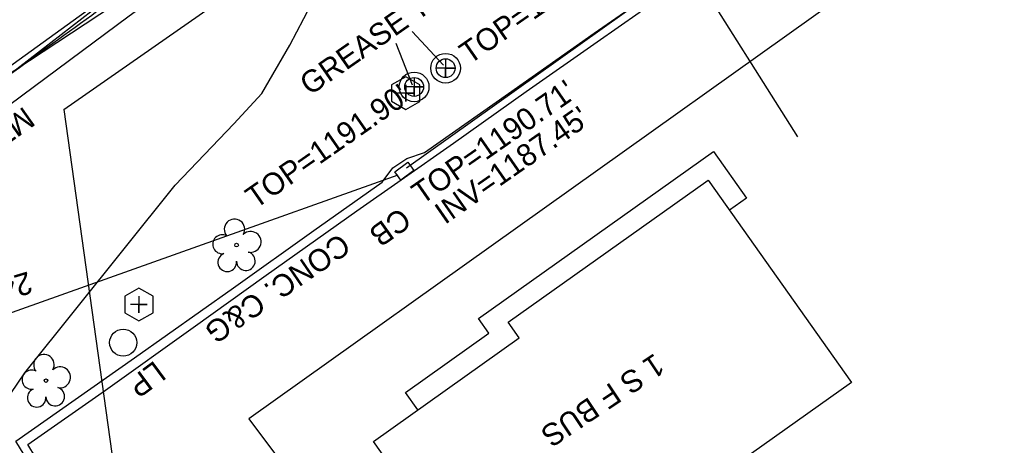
# Model space of a CAD drawing. Extents: x 1262092 to 1264624, y 774970 to 778314.
# Drawn here: x 1263560.4 to 1263737.4, y 776596.1 to 776673.4 of the extents above; entities that cross this region are included whole.
import ezdxf

# ---------------------------------------------------------------- set-up
doc = ezdxf.new("R2010")
doc.units = 0
for name, color, linetype in [('COGO Default Parcel', 7, 'Continuous'), ('Exist Horizontal Alignment Tick Small', 7, 'Continuous'), ('Exist Right of Way Line', 7, 'Continuous'), ('Exist Roads Curbs', 7, 'Continuous'), ('Exist Roads EOP', 7, 'Continuous'), ('Exist Roads EOP Other', 7, 'Continuous'), ('Exist Roads EOT', 7, 'Continuous'), ('Exist Structure Minor Catch Basin', 7, 'Continuous'), ('Exist Structure Minor Catch Basin Text', 7, 'Continuous'), ('Exist Structure Minor Catch Basin Top Elevation', 7, 'Continuous'), ('Exist Structure Minor Pipes RCP 15 Inch', 7, 'Continuous'), ('Exist Structure Minor Pipes RCP 24 Inch', 7, 'Continuous'), ('Exist Structure Minor Pipes RCP 24 Inch Invert', 7, 'Continuous'), ('Exist Structure Minor Pipes RCP 24 Inch Text', 7, 'Continuous'), ('Exist Utilities Gas UG Line SUE LOS B', 7, 'Continuous'), ('Exist Utilities Other Pole Text', 7, 'Continuous'), ('Exist Utilities Sanitary Sewer Clean-Out CELL', 7, 'Continuous'), ('Exist Utilities Sanitary Sewer Manhole CELL', 7, 'Continuous'), ('Exist Utilities Sanitary Sewer Manhole Leader', 7, 'Continuous'), ('Exist Utilities Sanitary Sewer Manhole Text', 7, 'Continuous'), ('Exist Utilities Telephone UG FO SUE LOS B', 7, 'Continuous'), ('Exist Utilities TV UG Cable SUE LOS B', 7, 'Continuous'), ('Exist Utilities Water UG Line SUE LOS B', 7, 'Continuous'), ('Prop EOT', 7, 'Continuous'), ('Prop Horizontal Alignment Direction Label', 7, 'Continuous'), ('Prop Shade Medium', 7, 'Continuous'), ('Sheet Plan Layout CELL', 7, 'Continuous'), ('Sheet Plot Border Outside CELL', 7, 'Continuous'), ('Typical Text Label CELL', 7, 'Continuous')]:
    doc.layers.add(name, color=color, linetype=linetype)

# ---------------------------------------------------------------- blocks, each defined once
blk = doc.blocks.new('EXIST UTILITIES SANITARY SEWER MANHOLE')
at = {"layer": 'Exist Utilities Sanitary Sewer Manhole CELL'}
blk.add_lwpolyline([(0, 0.03425), (0, -0.03425), (0, 0), (0.03425, 0), (-0.03425, 0)], dxfattribs=at)
for radius in [0.05389, 0.03425]:
    blk.add_circle((0, 0), radius, dxfattribs=at)
blk = doc.blocks.new('EXIST UTILITIES SANITARY SEWER CLEAN-OUT')
at = {"layer": 'Exist Utilities Sanitary Sewer Clean-Out CELL'}
blk.add_line((0, 0), (0, 0), dxfattribs=at)
blk.add_lwpolyline([(-0.0516, 0.0299), (-0.0517, -0.0297), (-0.0001, -0.0596), (0.0516, -0.0299), (0.0517, 0.0297), (0.0001, 0.0596)], close=True, dxfattribs=at)
blk.add_lwpolyline([(0, 0.0302), (0, -0.0302), (0, 0), (0.0302, 0), (-0.0302, 0)], dxfattribs=at)

msp = doc.modelspace()

# ---------------------------------------------------------------- linework, layer by layer
at = {"layer": 'COGO Default Parcel'}
for p, q in [((1263742.72, 776701.07), (1263602.12, 776600.93)), ((1263602.12, 776600.93), (1264624.2, 775243.33))]:
    msp.add_line(p, q, dxfattribs=at)
at = {"layer": 'Exist Horizontal Alignment Tick Small'}
for p, q in [((1263599.87, 776632.46), (1263599.87, 776632.46)), ((1263565.25, 776607.87), (1263565.25, 776607.87))]:
    msp.add_line(p, q, dxfattribs=at)
for centre in [(1263599.87, 776632.46), (1263565.25, 776607.87)]:
    msp.add_circle(centre, 0.326, dxfattribs=at)
for centre, radius, start, end in [((1263599.49, 776635.33), 1.86, 330.1651, 219.7134), ((1263602.42, 776633.04), 1.9, 257.1011, 134.1999), ((1263597.27, 776632.61), 1.73, 62.6636, 279.3457), ((1263601.55, 776629.56), 1.7, 181.2822, 74.56), ((1263598.17, 776629.34), 1.69, 111.5671, 6.231), ((1263564.87, 776610.75), 1.86, 330.1651, 219.7134), ((1263562.64, 776608.03), 1.73, 62.6636, 279.3457), ((1263567.8, 776608.46), 1.9, 257.1011, 134.1999), ((1263563.55, 776604.75), 1.69, 111.5671, 6.231), ((1263566.92, 776604.97), 1.7, 181.2822, 74.56)]:
    msp.add_arc(centre, radius, start, end, dxfattribs=at)
at = {"layer": 'Exist Right of Way Line'}
msp.add_line((1263568.46, 776657.05), (1263590.4, 776500.74), dxfattribs=at)
msp.add_lwpolyline([(1263568.46, 776657.05), (1263702.84, 776750.64)], dxfattribs=at)
at = {"layer": 'Exist Roads Curbs'}
msp.add_lwpolyline([(1263561.27, 776594.43), (1263559.79, 776596.9), (1263581.35, 776612), (1263599.3, 776624.7), (1263613.93, 776635.12), (1263626.33, 776643.89), (1263628.24, 776646.49), (1263630.82, 776648.18), (1263634, 776649.25), (1263649.25, 776659.95), (1263664.81, 776670.88), (1263681.21, 776682.3), (1263690.99, 776689.31), (1263693.46, 776691.09)], dxfattribs=at)
at = {"layer": 'Exist Roads EOP'}
msp.add_spline([(1263532.95, 776644.88), (1263556.37, 776661.77), (1263588.74, 776685.14), (1263625.33, 776711.31), (1263659.49, 776736.27), (1263691.33, 776758.54), (1263726.37, 776783.82), (1263756.25, 776805.33), (1263773.74, 776816.65), (1263781.38, 776820.01)], degree=3, dxfattribs=at)
at = {"layer": 'Exist Roads EOP Other'}
msp.add_lwpolyline([(1263563.33, 776593.99), (1263561.96, 776596.29), (1263576.06, 776606.15), (1263591.97, 776617.51), (1263605.25, 776627), (1263621.74, 776638.66), (1263629.78, 776644.28), (1263639.28, 776650.94), (1263652.49, 776660.3), (1263665.38, 776669.34), (1263680.66, 776680.07), (1263694.4, 776689.66), (1263697.91, 776691.81), (1263697.33, 776692.64), (1263718.16, 776706.69), (1263719.2, 776707.39), (1263725.24, 776711.12), (1263726.81, 776711.79), (1263727.66, 776712.06), (1263728.82, 776712.63), (1263730.53, 776713.94), (1263732.37, 776715.67), (1263734.72, 776717.25)], dxfattribs=at)
at = {"layer": 'Exist Roads EOT'}
msp.add_lwpolyline([(1263720.15, 776782.77), (1263652.29, 776732.34), (1263570.17, 776673.15), (1263507.29, 776627.83), (1263482.12, 776608.95)], dxfattribs=at)
at = {"layer": 'Exist Structure Minor Catch Basin'}
msp.add_lwpolyline([(1263629.7, 776644.25), (1263628.6, 776645.74), (1263630.99, 776647.51), (1263632.09, 776646.02), (1263629.7, 776644.25)], dxfattribs=at)
at = {"layer": 'Exist Structure Minor Pipes RCP 15 Inch'}
msp.add_line((1263722.4, 776711.58), (1263630.73, 776646.44), dxfattribs=at)
at = {"layer": 'Exist Structure Minor Pipes RCP 24 Inch'}
msp.add_line((1263501.71, 776599.84), (1263629.23, 776645.22), dxfattribs=at)
at = {"layer": 'Exist Utilities Gas UG Line SUE LOS B'}
msp.add_lwpolyline([(1263629.18, 776756.87), (1263651.04, 776727.99), (1263682.35, 776682.89), (1263701.79, 776652.11)], dxfattribs=at)
msp.add_lwpolyline([(1263629.18, 776756.87), (1263651.04, 776727.99), (1263682.35, 776682.89), (1263701.79, 776652.11)], dxfattribs=at)
msp.add_circle((1263579.27, 776614.76), 2.46, dxfattribs=at)
at = {"layer": 'Exist Utilities Sanitary Sewer Manhole Leader'}
for p, q in [((1263637.49, 776665.13), (1263631.78, 776671.19)), ((1263631.86, 776661.45), (1263628.88, 776669.05))]:
    msp.add_line(p, q, dxfattribs=at)
at = {"layer": 'Exist Utilities Telephone UG FO SUE LOS B'}
msp.add_lwpolyline([(1263374.75, 776678.22), (1263375.68, 776681.06), (1263379.13, 776682.39), (1263389.86, 776679.46), (1263415.53, 776664.61), (1263439.87, 776654.43), (1263458.67, 776649.03), (1263482.98, 776643.19), (1263509.47, 776637.5), (1263523.2, 776637.74), (1263558.6, 776663.43), (1263581.13, 776680.9), (1263585.35, 776686.02), (1263626.16, 776715.62), (1263668.08, 776742.82), (1263718.11, 776780.1)], dxfattribs=at)
at = {"layer": 'Exist Utilities TV UG Cable SUE LOS B'}
msp.add_lwpolyline([(1263537.75, 776574.54), (1263561.39, 776609.26), (1263588.74, 776643.36), (1263599.4, 776654.43), (1263604.44, 776659.94), (1263609.55, 776668.72), (1263617.19, 776683.32), (1263624.5, 776697.44), (1263665.8, 776724.26), (1263696.26, 776747.49), (1263728.48, 776775.18)], dxfattribs=at)
at = {"layer": 'Exist Utilities Water UG Line SUE LOS B'}
msp.add_lwpolyline([(1263347.21, 776507.23), (1263397.19, 776541.22), (1263457.64, 776583.33), (1263477.05, 776598.15), (1263485.24, 776605.23), (1263512.95, 776629.4), (1263525.59, 776641.3), (1263531.46, 776645.78), (1263577.52, 776675.99), (1263611.56, 776698.86), (1263659.68, 776735.07), (1263728.69, 776785.97)], dxfattribs=at)
at = {"layer": 'Prop Horizontal Alignment Direction Label'}
msp.add_lwpolyline([(1263632.79, 776602.56), (1263630.56, 776605.69), (1263645.73, 776616.47), (1263643.85, 776619.11), (1263686.5, 776649.43), (1263692.52, 776640.96), (1263689.45, 776638.78)], dxfattribs=at)
at = {"layer": 'Prop Shade Medium'}
msp.add_lwpolyline([(1263711.59, 776607.54), (1263675.65, 776582.06), (1263673.45, 776585.17), (1263646.54, 776566.1), (1263624.74, 776596.85), (1263651.24, 776615.63), (1263649.23, 776618.47), (1263685.58, 776644.24)], close=True, dxfattribs=at)
at = {"layer": 'Typical Text Label CELL'}
msp.add_lwpolyline([(1263702.14, 776763.29), (1263690.8, 776754.75), (1263665.88, 776736.16), (1263645.85, 776721.44), (1263625.64, 776706.72), (1263605.49, 776692.17), (1263580.35, 776673.99), (1263549.91, 776651.44)], dxfattribs=at)

# ---------------------------------------------------------------- block references
at = {"layer": 'Exist Utilities Sanitary Sewer Clean-Out CELL', "xscale": 50, "yscale": 50}
for p in [(1263630.6, 776660.03), (1263582.13, 776621.68)]:
    msp.add_blockref('EXIST UTILITIES SANITARY SEWER CLEAN-OUT', p, dxfattribs=at)
at = {"layer": 'Exist Utilities Sanitary Sewer Manhole CELL', "xscale": 50, "yscale": 50}
for p in [(1263637.85, 776664.55), (1263637.85, 776664.55), (1263632.13, 776661.15), (1263632.13, 776661.15)]:
    msp.add_blockref('EXIST UTILITIES SANITARY SEWER MANHOLE', p, dxfattribs=at)

# ---------------------------------------------------------------- texts
at = {"layer": 'Exist Structure Minor Catch Basin Text'}
msp.add_text('CB', height=4, rotation=215.4925, dxfattribs=at).set_placement((1263629.66, 776639.45))
at = {"layer": 'Exist Structure Minor Catch Basin Top Elevation'}
msp.add_text("TOP=1190.71'", height=4, rotation=34.8555, dxfattribs=at).set_placement((1263633.52, 776639.68))
at = {"layer": 'Exist Structure Minor Pipes RCP 24 Inch Invert'}
msp.add_text("INV=1187.45'", height=4, rotation=34.8555, dxfattribs=at).set_placement((1263637.72, 776636.09))
at = {"layer": 'Exist Structure Minor Pipes RCP 24 Inch Text'}
msp.add_text('24" RCP', height=4, rotation=196.7049, dxfattribs=at).set_placement((1263561.99, 776627.72))
at = {"layer": 'Exist Utilities Other Pole Text'}
msp.add_text('LP', height=4, rotation=216.5969, dxfattribs=at).set_placement((1263584.99, 776611.64))
at = {"layer": 'Exist Utilities Sanitary Sewer Manhole Text'}
for s, p in [("TOP=1191.85'", (1263642.19, 776665.14)), ('GREASE TRAP', (1263613.18, 776659.49)), ("TOP=1191.90'", (1263603.33, 776638.93))]:
    msp.add_text(s, height=4, rotation=34.8555, dxfattribs=at).set_placement(p)
at = {"layer": 'Prop EOT'}
msp.add_text('1 S F BUS', height=4, rotation=213.7739, dxfattribs=at).set_placement((1263675.82, 776612.95))
at = {"layer": 'Sheet Plan Layout CELL'}
msp.add_text('MTL', height=4, rotation=215.3071, dxfattribs=at).set_placement((1263561.27, 776657.71))
at = {"layer": 'Sheet Plot Border Outside CELL'}
msp.add_text('CONC. C&G', height=4, rotation=214.4661, dxfattribs=at).set_placement((1263618.7, 776634.77))

doc.saveas('drawing.dxf')
